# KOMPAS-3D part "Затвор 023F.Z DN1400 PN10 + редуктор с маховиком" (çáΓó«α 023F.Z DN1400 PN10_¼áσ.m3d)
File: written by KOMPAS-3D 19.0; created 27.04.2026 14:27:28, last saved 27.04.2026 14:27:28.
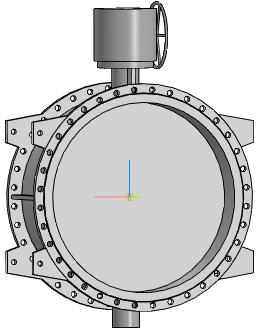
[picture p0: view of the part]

Document properties: Полное имя файла: ..\..\Затвор 023F.Z DN200-DN1600_с маховиком\Затвор 023F.Z DN1400 PN10 + редуктор с маховиком.a3d

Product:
- Part/product: Затвор 023F.Z DN1400 PN10 + редуктор с маховиком
    Масса: 3317.41

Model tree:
1. Операция без истории:1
